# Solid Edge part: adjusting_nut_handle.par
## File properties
Title: Adjusting nut handle
Author: vicky raina
Template: Normal.par
Last saved by: Robert a Rhodes jr
Revision: 4
Application: Solid Edge
Material: aluminum
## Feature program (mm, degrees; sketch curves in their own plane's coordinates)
sketch for "unnamed Protrusion 1" plane through (0, 0, 0) normal (0, -1, 0) x-axis (1, 0, 0)
  circle centre (0, 0) radius 9.5123
extrude "unnamed Protrusion 1" add finite 127 symmetric
chamfer "unnamed Chamfer 1"
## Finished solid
Body 1: solid body, 5 faces, 4 edges, 0 vertices.
  Faces by surface: cone 2, plane 2, cylinder 1
  Edges by curve: circle 4
Bounding box of the edges (mm): 19.025 x 127.000 x 19.025, from (-9.5123, -63.5, -9.5123) to (9.5123, 63.5, 9.5123).
Cylindrical faces by radius (mm): R9.5123 x1
Conical faces (half-angle, radius in mm at the cone's reference point): 45 deg R7.9375 x1, 45 deg R9.5123 x1
Planar faces by outward normal: +y 1, -y 1
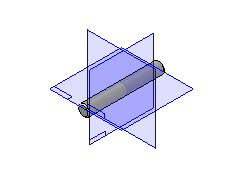
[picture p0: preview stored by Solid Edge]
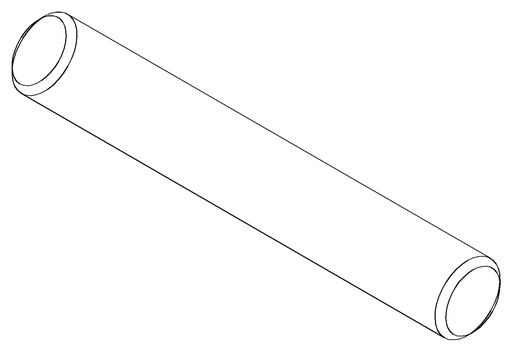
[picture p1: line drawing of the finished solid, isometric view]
